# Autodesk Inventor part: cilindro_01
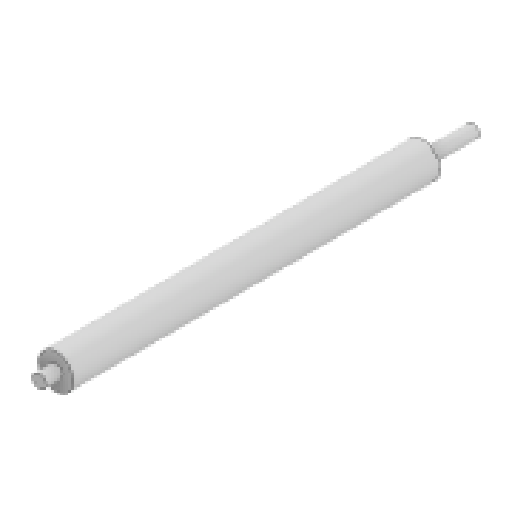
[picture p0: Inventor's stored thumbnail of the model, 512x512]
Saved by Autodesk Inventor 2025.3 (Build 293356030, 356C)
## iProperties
Created: 2025-09
Part Number: cilindro_01
Material: Plastica ABS
Document SubType Name: Modeling
Designer: R5800u
Density: 1.06 g/cm^3
Appearance: Liscia - Giallo
Author: R5800u
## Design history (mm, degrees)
sketch "Schizzo1"
  geometry: C1 r 10.5 at (0, 0); 1 further point
  constraints: 1 centre point, 1 coincident
  dimensions: "d0" = 21 diameter of C1
extrude "Estrusione1" new body sketch "Schizzo1" stored distance "d1" = 220; taper "d2" = 0 deg
sketch "Schizzo2"
  geometry: C1 r 4 at (0, 0); 1 further point
  constraints: 1 centre point, 1 coincident
  dimensions: "d3" = 8 diameter of C1
extrude "Estrusione2" join sketch "Schizzo2" distance "d4" = 10; taper "d5" = 0 deg
mirror "Speculare1"
sketch "Schizzo3"
  geometry: C1 r 4 at (0, 0) reference; 1 further point
extrude "Estrusione3" join sketch "Schizzo3" distance "d6" = 20; taper "d7" = 0 deg
sketch "Schizzo4"
  geometry: C1 r 4 at (0, 0) reference; C2 r 6 at (0, 0); 1 further point
  constraints: 1 centre point, 1 coincident
  dimensions: "d8" = 12 diameter of C2
node "Piano di lavoro1"
extrude "Estrusione4" join sketch "Schizzo4" stored distance "d9" = 20; taper "d10" = 0 deg
sketch "Schizzo5"
  geometry: C1 r 4 at (0, 0); 1 further point
  constraints: 1 centre point, 1 coincident
extrude "Estrusione5" join sketch "Schizzo5" distance "d11" = 10; taper "d12" = 0 deg
sketch "Schizzo6"
  geometry: C1 r 4 at (0, 0) reference; C2 r 6 at (0, 0); 1 further point
  constraints: 1 centre point, 1 coincident
  dimensions: "d13" = 12 diameter of C2
node "Piano di lavoro2"
extrude "Estrusione6" join sketch "Schizzo6" stored distance "d14" = 10; taper "d15" = 0 deg
node "Solido1"
